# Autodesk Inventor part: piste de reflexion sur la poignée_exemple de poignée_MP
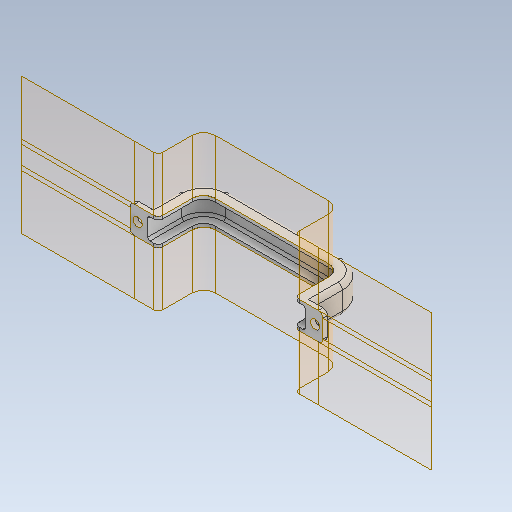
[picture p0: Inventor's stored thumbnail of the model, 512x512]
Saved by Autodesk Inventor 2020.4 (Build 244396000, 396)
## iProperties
Created: 2021-10
Part Number: piste de reflexion sur la poignée_exemple de poignée_MP
Material: Générique
Document SubType Name: Modeling
Designer: mel
Density: 1 g/cm^3
Appearance: Par défaut
Author: mel
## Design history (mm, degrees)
derived "exemple de poignée.ipt"
node "piste de reflexion sur la poignée_exemple de poignée_WP"
feature "Carreau délimité1" dims "d7" = 5, "d8" = 0
feature "Carreau délimité2" dims "d9" = 5, "d10" = 0
node "Face du plan de joint27" dims "Xmax" = 150, "Xmin" = -150, "Ymax" = 50, "Ymin" = -50, "Zmax" = 50, "Zmin" = -50
node "Face du plan de joint28" dims "Xmax" = 150, "Xmin" = -150, "Ymax" = 50, "Ymin" = -50, "Zmax" = 50, "Zmin" = -50
node "Face du plan de joint29" dims "Xmax" = 150, "Xmin" = -150, "Ymax" = 50, "Ymin" = -50, "Zmax" = 50, "Zmin" = -50
node "Face du plan de joint30" dims "Xmax" = 150, "Xmin" = -150, "Ymax" = 50, "Ymin" = -50, "Zmax" = 50, "Zmin" = -50
node "Face du plan de joint1" dims "Xmax" = 150, "Xmin" = -150, "Ymax" = 50, "Ymin" = -50, "Zmax" = 50, "Zmin" = -50
node "Face du plan de joint2" dims "Xmax" = 150, "Xmin" = -150, "Ymax" = 50, "Ymin" = -50, "Zmax" = 50, "Zmin" = -50
node "Face du plan de joint3" dims "Xmax" = 150, "Xmin" = -150, "Ymax" = 50, "Ymin" = -50, "Zmax" = 50, "Zmin" = -50
node "Face du plan de joint4" dims "Xmax" = 150, "Xmin" = -150, "Ymax" = 50, "Ymin" = -50, "Zmax" = 50, "Zmin" = -50
node "Face du plan de joint5" dims "Xmax" = 150, "Xmin" = -150, "Ymax" = 50, "Ymin" = -50, "Zmax" = 50, "Zmin" = -50
node "Face du plan de joint6" dims "Xmax" = 150, "Xmin" = -150, "Ymax" = 50, "Ymin" = -50, "Zmax" = 50, "Zmin" = -50
node "Face du plan de joint7" dims "Xmax" = 150, "Xmin" = -150, "Ymax" = 50, "Ymin" = -50, "Zmax" = 50, "Zmin" = -50
node "Face du plan de joint8" dims "Xmax" = 150, "Xmin" = -150, "Ymax" = 50, "Ymin" = -50, "Zmax" = 50, "Zmin" = -50
node "Face du plan de joint10" dims "Xmax" = 150, "Xmin" = -150, "Ymax" = 50, "Ymin" = -50, "Zmax" = 50, "Zmin" = -50
node "Face du plan de joint12" dims "Xmax" = 150, "Xmin" = -150, "Ymax" = 50, "Ymin" = -50, "Zmax" = 50, "Zmin" = -50
node "Face du plan de joint13" dims "Xmax" = 150, "Xmin" = -150, "Ymax" = 50, "Ymin" = -50, "Zmax" = 50, "Zmin" = -50
node "Face du plan de joint14" dims "Xmax" = 150, "Xmin" = -150, "Ymax" = 50, "Ymin" = -50, "Zmax" = 50, "Zmin" = -50
node "Face du plan de joint15" dims "Xmax" = 150, "Xmin" = -150, "Ymax" = 50, "Ymin" = -50, "Zmax" = 50, "Zmin" = -50
node "Face du plan de joint16" dims "Xmax" = 150, "Xmin" = -150, "Ymax" = 50, "Ymin" = -50, "Zmax" = 50, "Zmin" = -50
node "Face du plan de joint17" dims "Xmax" = 150, "Xmin" = -150, "Ymax" = 50, "Ymin" = -50, "Zmax" = 50, "Zmin" = -50
node "Face du plan de joint18" dims "Xmax" = 150, "Xmin" = -150, "Ymax" = 50, "Ymin" = -50, "Zmax" = 50, "Zmin" = -50
node "Face du plan de joint19" dims "Xmax" = 150, "Xmin" = -150, "Ymax" = 50, "Ymin" = -50, "Zmax" = 50, "Zmin" = -50
node "Face du plan de joint20" dims "Xmax" = 150, "Xmin" = -150, "Ymax" = 50, "Ymin" = -50, "Zmax" = 50, "Zmin" = -50
node "Face du plan de joint21" dims "Xmax" = 150, "Xmin" = -150, "Ymax" = 50, "Ymin" = -50, "Zmax" = 50, "Zmin" = -50
node "Face du plan de joint22" dims "Xmax" = 150, "Xmin" = -150, "Ymax" = 50, "Ymin" = -50, "Zmax" = 50, "Zmin" = -50
node "Face du plan de joint23" dims "Xmax" = 150, "Xmin" = -150, "Ymax" = 50, "Ymin" = -50, "Zmax" = 50, "Zmin" = -50
node "Face du plan de joint24" dims "Xmax" = 150, "Xmin" = -150, "Ymax" = 50, "Ymin" = -50, "Zmax" = 50, "Zmin" = -50
node "Face du plan de joint25" dims "Xmax" = 150, "Xmin" = -150, "Ymax" = 50, "Ymin" = -50, "Zmax" = 50, "Zmin" = -50
node "Face du plan de joint26" dims "Xmax" = 150, "Xmin" = -150, "Ymax" = 50, "Ymin" = -50, "Zmax" = 50, "Zmin" = -50
feature "Séparation d'empreinte1"
feature "Solide1::exemple de poignée.ipt"
tag "FonctionRepérage1"
feature "Solide1::piste de reflexion sur la poignée_exemple de poigné"
tag "FonctionRepérage2"
body "Srf1"
body "Srf2"
node "Solide3"
node "Solide4"
node "Solide1"
feature "exemple de poignée.ipt_Corps"
node "Solide2"
feature "piste de reflexion sur la poignée_exemple de poignée_WP_Corp"
feature "Surface1"
body "Srf3"
feature "Surface2"
body "Srf4"
feature "Surface3"
body "Srf5"
feature "Surface4"
body "Srf6"
feature "Surface5"
body "Srf7"
feature "Surface6"
body "Srf8"
feature "Surface7"
body "Srf9"
feature "Surface8"
body "Srf10"
feature "Surface10"
body "Srf12"
feature "Surface12"
body "Srf14"
feature "Surface13"
body "Srf15"
feature "Surface14"
body "Srf16"
feature "Surface15"
body "Srf17"
feature "Surface16"
body "Srf18"
feature "Surface17"
body "Srf19"
feature "Surface18"
body "Srf20"
feature "Surface19"
body "Srf21"
feature "Surface20"
body "Srf22"
feature "Surface21"
body "Srf23"
feature "Surface22"
body "Srf24"
feature "Surface23"
body "Srf25"
feature "Surface24"
body "Srf26"
feature "Surface25"
body "Srf27"
feature "Surface26"
body "Srf28"
feature "Surface27"
body "Srf29"
feature "Surface28"
body "Srf30"
feature "Surface29"
body "Srf31"
feature "Surface30"
body "Srf32"
other parameters: "d6" = 0
